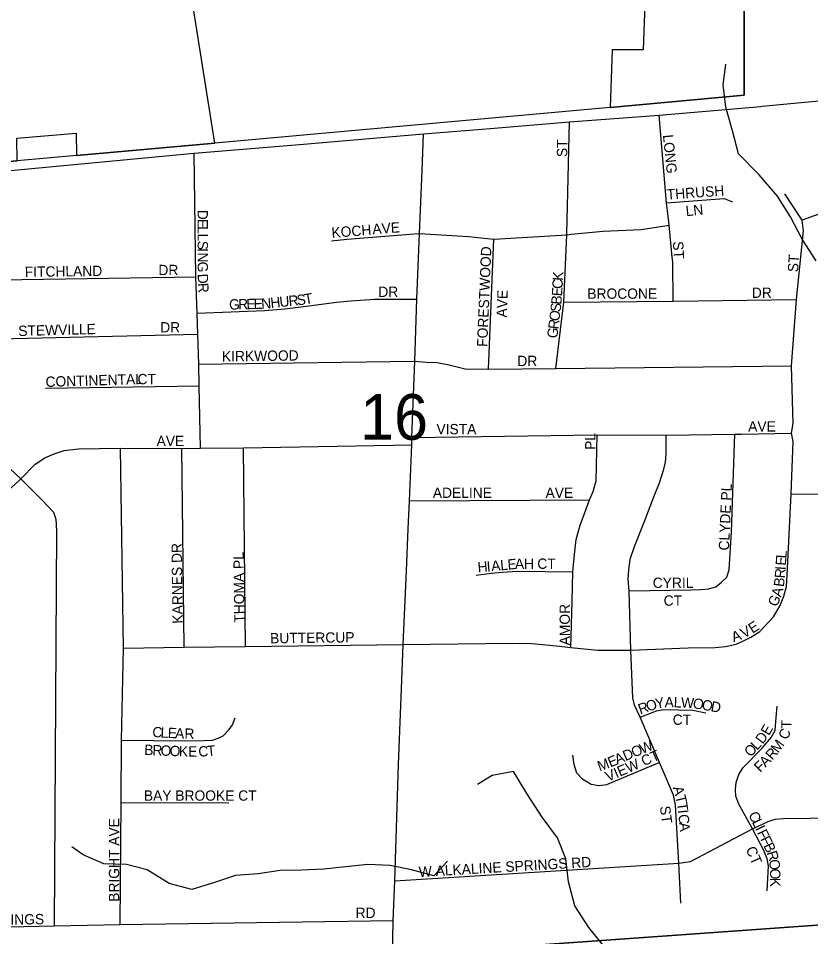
# Model space of a CAD drawing. Extents: x 8.5 to 81.5, y -1.2 to 22.4.
# Drawn here: x 51.374 to 52.1, y 18.88 to 19.722 of the extents above; entities that cross this region are included whole.
import ezdxf

# ---------------------------------------------------------------- set-up
doc = ezdxf.new("R2010")
doc.units = 0
for name, color, linetype in [('GM_X_City_Street', 7, 'Continuous'), ('GM_X_City_Street_Text', 7, 'Continuous'), ('GM_X_Corporation', 7, 'Continuous'), ('GM_X_Minor_River', 7, 'Continuous'), ('GM_X_Section', 7, 'Continuous'), ('GM_X_Section_Text', 7, 'Continuous'), ('GM_X_US_Route', 7, 'Continuous')]:
    doc.layers.add(name, color=color, linetype=linetype)

msp = doc.modelspace()

# ---------------------------------------------------------------- linework, layer by layer
at = {"layer": 'GM_X_City_Street'}
for points in [[(51.87685, 19.52408), (51.87925, 19.62701)], [(51.96945, 19.54287), (51.96828, 19.55263), (51.96146, 19.63302)], [(51.73148, 19.25396), (51.73263, 19.27961), (51.7347, 19.33101), (51.7347, 19.33774), (51.73741, 19.4076), (51.73915, 19.4644), (51.74163, 19.52459), (51.74411, 19.58198), (51.74541, 19.61584)], [(51.54081, 19.32779), (51.53976, 19.38464), (51.53939, 19.40481), (51.53837, 19.43236), (51.53791, 19.45166), (51.53665, 19.48503), (51.53494, 19.59813)], [(52.06638, 19.17336), (52.07218, 19.18307), (52.0759, 19.19225), (52.0783, 19.20122), (52.07896, 19.21161), (52.08257, 19.28608), (52.08432, 19.33398), (52.08301, 19.34164), (52.08432, 19.3506), (52.08289, 19.4033), (52.08738, 19.46412), (52.09372, 19.5271), (52.09263, 19.53695), (52.07666, 19.561)], [(51.96828, 19.55263), (52.02097, 19.55676), (52.02885, 19.55364)], [(51.97353, 19.50285), (51.97071, 19.53237), (51.96945, 19.54287)], [(52.15521, 19.49645), (52.16173, 19.54655), (52.1223, 19.54744), (52.09263, 19.53695)], [(51.74091, 19.52453), (51.74163, 19.52459), (51.76659, 19.52307), (51.78652, 19.52177), (51.80981, 19.51949), (51.87684, 19.52352), (51.88094, 19.52392)], [(51.88094, 19.52392), (51.91025, 19.52677), (51.93092, 19.52776)], [(51.93092, 19.52776), (51.9451, 19.52843), (51.97071, 19.53237)], [(51.66098, 19.51781), (51.67528, 19.5193), (51.74091, 19.52453)], [(51.80496, 19.40023), (51.80981, 19.51949)], [(51.86685, 19.40102), (51.87406, 19.46182), (51.87684, 19.52352), (51.87685, 19.52408)], [(51.97432, 19.46265), (51.97394, 19.49857), (51.97353, 19.50285)], [(51.35682, 19.48211), (51.53665, 19.48503)], [(51.53791, 19.45166), (51.59972, 19.45392), (51.61825, 19.45557), (51.64019, 19.45828), (51.66556, 19.46159), (51.67901, 19.463), (51.7005, 19.46435), (51.7103, 19.46435), (51.73915, 19.4644)], [(51.87406, 19.46182), (51.97432, 19.46265), (52.08738, 19.46412)], [(51.33929, 19.4389), (51.34758, 19.43158), (51.35567, 19.42811), (51.53837, 19.43236)], [(51.67039, 19.40665), (51.73741, 19.4076), (51.74093, 19.40735)], [(51.74093, 19.40735), (51.74824, 19.40684), (51.75803, 19.40638), (51.76905, 19.4044), (51.78352, 19.40063), (51.80496, 19.40023), (51.86685, 19.40102), (52.08289, 19.4033)], [(51.53939, 19.40481), (51.67039, 19.40665)], [(51.53976, 19.38464), (51.39869, 19.38247)], [(51.7347, 19.33774), (51.90478, 19.33998), (51.96803, 19.33976), (52.03092, 19.34067), (52.0371, 19.34076), (52.08301, 19.34164)], [(51.88059, 19.14533), (51.88177, 19.18726), (51.88249, 19.21444), (51.88376, 19.23037), (51.88535, 19.24412), (51.88904, 19.25721), (51.89301, 19.26809), (51.89769, 19.28041), (51.90108, 19.28802), (51.90372, 19.29794), (51.90478, 19.33998)], [(51.97954, 18.94754), (51.97645, 19.00096), (51.9747, 19.01001), (51.96183, 19.03988), (51.94404, 19.08134), (51.9388, 19.09246), (51.93721, 19.09897), (51.93554, 19.14282), (51.93388, 19.19722), (51.93308, 19.20787), (51.9336, 19.21597), (51.93506, 19.2263), (51.93888, 19.23789), (51.94775, 19.26002), (51.95738, 19.28484), (51.96191, 19.2962), (51.96565, 19.30859), (51.96731, 19.31518), (51.96787, 19.3228), (51.96803, 19.33976)], [(52.01876, 19.20497), (52.02354, 19.20979), (52.02573, 19.21637), (52.02775, 19.25116), (52.03092, 19.34067)], [(51.25939, 19.33056), (51.32288, 19.3313), (51.33704, 19.33142), (51.34253, 19.32971), (51.34656, 19.32739), (51.37599, 19.29965), (51.39553, 19.28063), (51.40602, 19.26915), (51.40822, 19.2628), (51.40883, 19.25205), (51.40683, 18.88998)], [(51.37528, 19.29898), (51.37599, 19.29965), (51.38915, 19.31308), (51.39801, 19.31889), (51.40673, 19.32281), (51.41601, 19.32571), (51.42909, 19.32731), (51.46743, 19.32774), (51.52363, 19.32756), (51.54081, 19.32779), (51.58027, 19.32833), (51.7347, 19.33101)], [(51.46707, 18.89134), (51.46812, 19.00313), (51.46848, 19.0604), (51.47015, 19.14464), (51.46743, 19.32774)], [(51.52594, 19.14539), (51.52363, 19.32756)], [(51.58229, 19.14615), (51.58027, 19.32833)], [(51.18519, 19.26692), (51.18797, 19.26692), (51.29737, 19.26835), (51.31509, 19.26864), (51.33063, 19.27067), (51.34486, 19.27634), (51.35909, 19.28374), (51.37528, 19.29898)], [(52.08257, 19.28608), (52.22886, 19.28586)], [(51.73263, 19.27961), (51.89769, 19.28041)], [(51.72583, 19.12331), (51.72677, 19.14809), (51.72974, 19.2155), (51.73148, 19.25396)], [(51.79367, 19.2114), (51.8076, 19.21323), (51.81766, 19.21431), (51.83148, 19.21516), (51.88249, 19.21444)], [(51.93388, 19.19722), (51.9904, 19.19797), (51.99966, 19.19834), (52.00684, 19.19882), (52.01347, 19.20074), (52.01876, 19.20497)], [(51.47015, 19.14464), (51.52594, 19.14539), (51.58229, 19.14615), (51.72677, 19.14809), (51.82729, 19.14927), (51.84469, 19.14897), (51.86742, 19.14661), (51.88059, 19.14533), (51.90528, 19.14267), (51.93554, 19.14282), (51.98817, 19.14501), (52.01297, 19.14533), (52.02244, 19.14624), (52.03215, 19.14838), (52.03835, 19.15113), (52.04568, 19.1548), (52.05369, 19.15999), (52.06638, 19.17336)], [(51.71222, 18.35895), (51.71499, 18.68889), (51.71556, 18.78118), (51.71744, 18.89515), (51.71909, 18.93134), (51.7226, 19.03785), (51.72583, 19.12331)], [(51.94404, 19.08134), (51.95896, 19.0872), (51.96554, 19.08842), (51.99234, 19.08768), (52.00428, 19.08525)], [(52.04695, 18.979), (52.03443, 19.00159), (52.03189, 19.0089), (52.03157, 19.01494), (52.03221, 19.02161), (52.03443, 19.02891), (52.03856, 19.03527), (52.05604, 19.05306), (52.0643, 19.06259), (52.06779, 19.06927), (52.06875, 19.08102), (52.0697, 19.09151)], [(51.46848, 19.0604), (51.52707, 19.05967), (51.54433, 19.05982), (51.55187, 19.0604), (51.55724, 19.062), (51.56159, 19.06431), (51.56725, 19.07012), (51.57029, 19.07418), (51.57261, 19.08071)], [(51.96183, 19.03988), (51.91314, 19.01944), (51.90656, 19.01847), (51.90606, 19.01847), (51.89924, 19.01969), (51.89144, 19.02432), (51.88608, 19.03017), (51.88365, 19.03797), (51.88243, 19.0465)], [(51.46812, 19.00313), (51.56681, 19.00297)], [(51.71909, 18.93134), (51.97954, 18.94754), (51.99021, 18.94922), (52.04695, 18.979), (52.06156, 18.98574), (52.06788, 18.98786), (52.07559, 18.98835), (52.12459, 18.98906), (52.21756, 18.98994)], [(52.06048, 18.92216), (52.06175, 18.94504), (52.06048, 18.95139), (52.05762, 18.95902), (52.04695, 18.979)], [(51.98146, 18.9108), (51.97954, 18.94754)], [(50.97208, 18.88635), (51.00926, 18.88596), (51.08581, 18.88617), (51.18527, 18.88702), (51.32318, 18.88832), (51.40683, 18.88998), (51.46707, 18.89134), (51.71744, 18.89515)]]:
    msp.add_lwpolyline(points, dxfattribs=at)
at = {"layer": 'GM_X_Corporation'}
for points in [[(52.25936, 21.01123), (52.2567, 20.86959), (52.25158, 20.86932), (52.23976, 20.8687), (52.27094, 19.9771), (52.217, 19.97523), (52.21768, 19.95576), (52.27298, 19.92635), (52.27419, 19.89183), (52.23539, 19.89048), (52.23716, 19.83987), (52.15793, 19.84059), (52.15789, 19.7505), (52.03952, 19.75051), (52.03953, 19.65129), (51.91664, 19.6402), (51.55407, 19.60748), (51.42733, 19.59604), (51.3727, 19.59111), (49.93264, 19.46099)], [(49.93264, 19.46099), (51.3727, 19.59111), (51.37231, 19.61199), (51.42697, 19.61665), (51.42733, 19.59604), (51.55407, 19.60748), (51.52016, 19.82136), (51.54761, 19.84881), (51.9245, 19.84882), (51.95067, 19.80163), (51.94688, 19.69284), (51.91847, 19.69284), (51.91664, 19.6402), (52.03953, 19.65129), (52.03952, 19.75051), (52.15789, 19.7505)]]:
    msp.add_lwpolyline(points, dxfattribs=at)
at = {"layer": 'GM_X_Minor_River'}
for points in [[(52.10545, 19.49952), (52.09252, 19.51928), (52.08187, 19.53979), (52.07008, 19.55878), (52.05334, 19.57853), (52.03433, 19.59753), (52.02862, 19.6188), (52.02253, 19.64046), (52.02025, 19.66097), (52.02253, 19.67996)], [(52.11768, 18.85186), (52.09753, 18.85756), (52.07699, 18.85984), (52.05608, 18.85833), (52.03516, 18.85605), (52.01501, 18.85377), (51.99334, 18.84921), (51.97318, 18.84656), (51.95341, 18.84542), (51.93439, 18.8496), (51.91272, 18.86935), (51.89712, 18.88872), (51.88419, 18.90848), (51.87849, 18.93051), (51.87582, 18.9514), (51.86821, 18.97078), (51.85414, 18.98977), (51.84007, 19.01142), (51.8279, 19.03155), (51.8085, 19.02775), (51.79479, 19.01974)], [(51.76754, 18.94927), (51.7549, 18.93583), (51.73436, 18.94152), (51.71497, 18.94532), (51.69443, 18.94646), (51.6739, 18.94418), (51.65412, 18.9419), (51.63359, 18.94114), (51.61382, 18.94076), (51.59366, 18.93772), (51.57313, 18.9362), (51.55373, 18.92974), (51.53282, 18.92328), (51.51229, 18.92898), (51.49213, 18.94151), (51.47312, 18.94644), (51.4522, 18.94682), (51.43319, 18.95518), (51.42292, 18.96239)]]:
    msp.add_lwpolyline(points, dxfattribs=at)
at = {"layer": 'GM_X_Section'}
for points in [[(52.28397, 19.8673), (52.22193, 19.20227), (52.2136, 18.89831), (51.6895, 18.86113), (51.22018, 18.85778), (51.2184, 19.37023), (51.23908, 19.86864)], [(52.2136, 18.89831), (52.21491, 17.8371), (51.21175, 17.84266), (51.22018, 18.85778), (51.6895, 18.86113)]]:
    msp.add_lwpolyline(points, close=True, dxfattribs=at)
at = {"layer": 'GM_X_US_Route'}
for points in [[(52.05585, 19.64124), (52.15679, 19.65085), (52.26596, 19.66055), (52.33754, 19.66771), (52.40081, 19.67283), (52.4644, 19.67804)], [(51.1273, 19.56184), (51.20147, 19.56862), (51.3602, 19.5816), (51.53494, 19.59813), (51.63523, 19.60658), (51.74541, 19.61584), (51.80651, 19.62072), (51.87925, 19.62701), (51.96146, 19.63302), (52.05486, 19.64115), (52.05585, 19.64124)]]:
    msp.add_lwpolyline(points, dxfattribs=at)

# ---------------------------------------------------------------- texts
at = {"layer": 'GM_X_City_Street_Text'}
for s, height, rotation, p in [('ST', 0.00947, 90, (51.87717, 19.59466)), ('LONG', 0.00947, 275.85261, (51.96489, 19.61484)), ('THRUSH', 0.00947, 4.08728, (51.96883, 19.55561)), ('LN', 0.00947, 6.01679, (51.98629, 19.54041)), ('D', 0.00947, 270.02187, (51.53824, 19.54633)), ('E', 0.00947, 270, (51.53824, 19.538)), ('AVE', 0.00947, 3.94312, (51.69883, 19.52394)), ('L', 0.00947, 270.02058, (51.53824, 19.53133)), ('KOCH', 0.00947, 4.39784, (51.66139, 19.52061)), ('S', 0.00947, 270.02058, (51.53824, 19.51799)), ('L', 0.00947, 270, (51.53824, 19.52466)), ('ST', 0.00947, 273.36421, (51.97407, 19.51727)), ('I', 0.00947, 270, (51.53825, 19.51133)), ('FORESTWOOD', 0.00947, 87.58802, (51.80384, 19.42057)), ('N', 0.00947, 270.01537, (51.53825, 19.50716)), ('ST', 0.00947, 86.42535, (52.08884, 19.48894)), ('FITCHLAND', 0.00947, 0.72484, (51.37977, 19.48478)), ('DR', 0.00947, 0.00001, (51.50229, 19.48644)), ('G', 0.00947, 270.01537, (51.53825, 19.49882)), ('D', 0.00947, 272.07816, (51.53826, 19.48762)), ('C', 0.00947, 86.73644, (51.87282, 19.47361)), ('K', 0.00947, 86.71953, (51.87325, 19.4811)), ('R', 0.00947, 273.31876, (51.53857, 19.47907)), ('DR', 0.00947, 0.00001, (51.70395, 19.46645)), ('E', 0.00947, 86.63397, (51.87243, 19.46693)), ('BROCONE', 0.00947, 0.00001, (51.89562, 19.46478)), ('DR', 0.00947, 0.00001, (52.04645, 19.46561)), ('H', 0.00947, 5.93822, (51.6055, 19.45623)), ('U', 0.00947, 5.97018, (51.6138, 19.45709)), ('R', 0.00947, 6.01823, (51.6221, 19.45796)), ('S', 0.00947, 6.07107, (51.62957, 19.45875)), ('T', 0.00947, 10.12158, (51.63692, 19.45956)), ('AVE', 0.00947, 88.02609, (51.82179, 19.4475)), ('B', 0.00947, 85.12617, (51.87177, 19.45919)), ('G', 0.00947, 1.50801, (51.56724, 19.45478)), ('R', 0.00947, 1.5019, (51.57557, 19.455)), ('E', 0.00947, 1.50091, (51.58307, 19.4552)), ('E', 0.00947, 1.53908, (51.58974, 19.45537)), ('N', 0.00947, 4.28194, (51.5969, 19.45558)), ('S', 0.00947, 83.0715, (51.87093, 19.45221)), ('O', 0.00947, 83.07355, (51.86993, 19.44393)), ('STEWVILLE', 0.00947, 1.46801, (51.37391, 19.43061)), ('DR', 0.00947, 0.00001, (51.50395, 19.43394)), ('R', 0.00947, 83.06173, (51.86902, 19.43649)), ('G', 0.00947, 83.07561, (51.86802, 19.42822)), ('KIRKWOOD', 0.00947, 0.74365, (51.5606, 19.40728)), ('DR', 0.00947, 0.00001, (51.83145, 19.40311)), ('CONTINENTAL', 0.0094697, 1.75245, (51.3989, 19.38395)), ('CT', 0.00947, 0.00001, (51.48312, 19.38645)), ('VISTA', 0.00947, 0.00001, (51.75729, 19.34061)), ('AVE', 0.00947, 0.00001, (52.04312, 19.34311)), ('PL', 0.00947, 90, (51.90301, 19.32633)), ('AVE', 0.00947, 0.00001, (51.50062, 19.32978)), ('ADELINE', 0.00947, 0.00001, (51.75395, 19.28228)), ('AVE', 0.00947, 0.00001, (51.85729, 19.28228)), ('CLYDE PL', 0.00947, 87.39818, (52.02551, 19.23392)), ('KARNES DR', 0.00947, 90.7341, (51.52467, 19.16714)), ('THOMA PL', 0.00947, 90.8065, (51.58134, 19.16797)), ('L', 0.00947, 85.92606, (52.07815, 19.22667)), ('H', 0.00947, 5.27557, (51.79545, 19.21394)), ('I', 0.00947, 5.30406, (51.80376, 19.2147)), ('A', 0.00947, 5.27557, (51.8079, 19.21509)), ('L', 0.00947, 5.28238, (51.8162, 19.21585)), ('E', 0.00947, 4.92476, (51.82282, 19.21647)), ('A', 0.00947, 1.66155, (51.82932, 19.21703)), ('H', 0.00947, 0.06558, (51.83758, 19.21727)), ('CT', 0.00947, 0.00001, (51.84979, 19.21728)), ('E', 0.00947, 85.93654, (52.07767, 19.22002)), ('R', 0.00947, 85.66371, (52.07681, 19.20834)), ('I', 0.00947, 85.90039, (52.07737, 19.21586)), ('CYRIL', 0.00947, 0.00001, (51.95562, 19.19978)), ('B', 0.00947, 82.7918, (52.07581, 19.20039)), ('A', 0.00947, 74.10215, (52.07321, 19.19084)), ('CT', 0.00947, 0.00001, (51.96562, 19.18349)), ('G', 0.00947, 66.07523, (52.06934, 19.18186)), ('AMOR', 0.00947, 90, (51.87967, 19.14716)), ('V', 0.00947, 28.15723, (52.03906, 19.15334)), ('E', 0.00947, 32.75696, (52.04712, 19.1577)), ('BUTTERCUP', 0.00947, 0.70695, (51.60476, 19.14895)), ('A', 0.00947, 19.54795, (52.02979, 19.14993)), ('O', 0.00947, 18.62158, (51.95124, 19.0863)), ('Y', 0.00947, 11.03989, (51.95882, 19.08888)), ('A', 0.00947, 359.30051, (51.96649, 19.09043)), ('L', 0.00947, 358.08721, (51.97476, 19.09033)), ('W', 0.00947, 357.27529, (51.98139, 19.0901)), ('O', 0.00947, 351.40007, (51.99196, 19.08961)), ('O', 0.00947, 349.71471, (52.00012, 19.08838)), ('D', 0.00947, 349.6932, (52.00832, 19.08689)), ('R', 0.00947, 19.20294, (51.94418, 19.08384)), ('CT', 0.00947, 0.00001, (51.97395, 19.07432)), ('C', 0.00947, 356.93871, (51.49655, 19.06311)), ('L', 0.00947, 356.9111, (51.50404, 19.06271)), ('E', 0.00947, 356.93497, (51.5107, 19.06235)), ('A', 0.00947, 357.13312, (51.5174, 19.06199)), ('R', 0.00947, 359.21014, (51.52609, 19.06156)), ('E', 0.00947, 60.62683, (52.06225, 19.06391)), ('C', 0.00947, 66.47272, (52.07902, 19.05999)), ('T', 0.00947, 88.7128, (52.08287, 19.07076)), ('D', 0.00947, 52.69945, (52.05641, 19.05609)), ('B', 0.00947, 357.44926, (51.48914, 19.04684)), ('R', 0.00947, 357.47407, (51.49664, 19.0465)), ('O', 0.00947, 357.46393, (51.50413, 19.04617)), ('O', 0.00947, 357.7073, (51.5125, 19.0458)), ('K', 0.00947, 358.22509, (51.52092, 19.04546)), ('E', 0.00947, 359.64433, (51.52951, 19.0452)), ('C', 0.00947, 1.81056, (51.53906, 19.04519)), ('T', 0.00947, 6.19619, (51.54735, 19.04549)), ('O', 0.00947, 22.83875, (51.93827, 19.04422)), ('W', 0.00947, 22.8255, (51.94595, 19.04745)), ('O', 0.00947, 45.60276, (52.04521, 19.04428)), ('L', 0.00947, 47.12247, (52.05123, 19.05043)), ('M', 0.00947, 54.12335, (52.07071, 19.04785)), ('VIEW CT', 0.00947, 23.46085, (51.91456, 19.02198)), ('E', 0.00947, 22.92724, (51.91678, 19.03515)), ('A', 0.00947, 22.82835, (51.92291, 19.03775)), ('D', 0.00947, 22.83875, (51.93059, 19.04098)), ('A', 0.00947, 45.81184, (52.05902, 19.03505)), ('R', 0.00947, 49.08577, (52.06522, 19.04147)), ('M', 0.00947, 19.9442, (51.90688, 19.03154)), ('F', 0.00947, 45.03863, (52.05421, 19.03024)), ('BAY BROOKE CT', 0.0094697, 0.00001, (51.48895, 19.00478)), ('A', 0.00947, 285.32989, (51.974, 19.01682)), ('T', 0.00947, 284.12901, (51.97619, 19.00883)), ('T', 0.00947, 278.22282, (51.97777, 19.00262)), ('ST', 0.00947, 277.59084, (51.96207, 18.99942)), ('I', 0.00947, 275.64969, (51.97871, 18.99613)), ('C', 0.00947, 295.93522, (52.04305, 18.99211)), ('BRIGHT AVE', 0.00947, 90, (51.46634, 18.91216)), ('C', 0.00947, 275.35055, (51.97912, 18.992)), ('L', 0.00947, 295.92969, (52.04633, 18.98537)), ('A', 0.00947, 275.35866, (51.97982, 18.98453)), ('I', 0.00947, 295.92, (52.04925, 18.97937)), ('F', 0.00947, 295.93687, (52.05107, 18.97562)), ('F', 0.00947, 295.92969, (52.05399, 18.96963)), ('CT', 0.00947, 293.96362, (52.04069, 18.96044)), ('B', 0.00947, 295.21793, (52.05689, 18.96366)), ('W ALKALINE SPRINGS RD', 0.0094697, 3.36586, (51.74135, 18.93478)), ('R', 0.00947, 287.89735, (52.05997, 18.95717)), ('O', 0.00947, 277.03286, (52.06217, 18.9505)), ('O', 0.00947, 270.43721, (52.06317, 18.94252)), ('K', 0.00947, 270, (52.06324, 18.9342)), ('RD', 0.00947, 0.00001, (51.68312, 18.89728)), ('SPRINGS', 0.00947, 1.00455, (51.34059, 18.89061))]:
    msp.add_text(s, height=height, rotation=rotation, dxfattribs=at).set_placement(p)
at = {"layer": 'GM_X_Section_Text'}
msp.add_text('16', height=0.041856, rotation=0.00001, dxfattribs=at).set_placement((51.68729, 19.33556))

doc.saveas('drawing.dxf')
